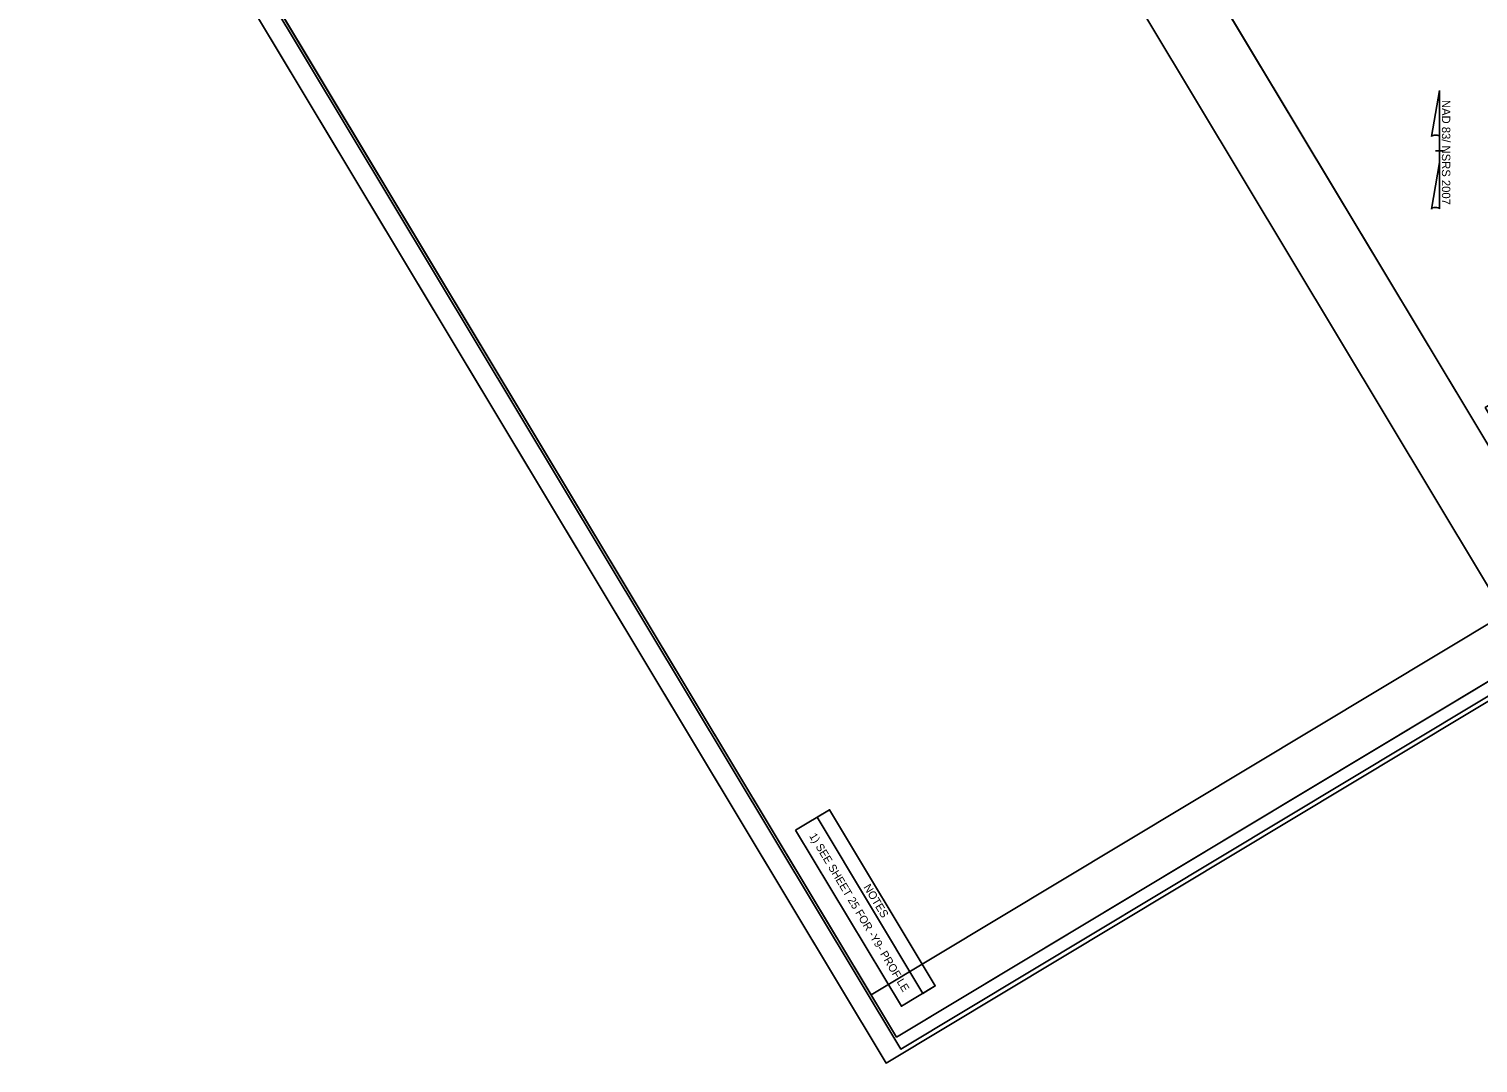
# Model space of a CAD drawing. Extents: x 1778994 to 1781413, y 814194 to 816432.
# Drawn here: x 1778994 to 1780460, y 814194 to 815240 of the extents above; entities that cross this region are included whole.
import ezdxf

# ---------------------------------------------------------------- set-up
doc = ezdxf.new("R2010")
doc.units = 0
for name, color, linetype in [('Matchline', 7, 'Continuous'), ('Prop DSN Text', 7, 'Continuous'), ('Prop Grid Mask', 7, 'Continuous'), ('Prop North Arrow NAD83 for Plan Sheets CELL', 7, 'Continuous'), ('Sheet Clip Boundary CELL', 7, 'Continuous'), ('Sheet Cutting Line CELL', 7, 'Continuous'), ('Sheet Layout Plan Border', 7, 'Continuous'), ('Sheet Plan CELL', 7, 'Continuous'), ('Sheet Plan Layout CELL', 7, 'Continuous'), ('Sheet Plot Border Inside CELL', 7, 'Continuous'), ('Sheet Plot Border Outside CELL', 7, 'Continuous')]:
    doc.layers.add(name, color=color, linetype=linetype)

msp = doc.modelspace()

# ---------------------------------------------------------------- linework, layer by layer
at = {"layer": 'Matchline'}
msp.add_line((1779828.9, 815886.5), (1780452.5, 814848.7), dxfattribs=at)
at = {"layer": 'Prop Grid Mask'}
for points in [[(1779769.3, 814429.8), (1779876.4, 814251.7), (1779910.7, 814272.3), (1779803.7, 814450.5)], [(1779791.2, 814443), (1779898.2, 814264.8), (1779910.7, 814272.3), (1779803.7, 814450.5)]]:
    msp.add_lwpolyline(points, close=True, dxfattribs=at)
at = {"layer": 'Prop North Arrow NAD83 for Plan Sheets CELL'}
for p, q in [((1780412.6, 815131.6), (1780420.8, 815178)), ((1780420.9, 815178), (1780420.8, 815178)), ((1780420.9, 815178), (1780420.8, 815178)), ((1780420.9, 815178), (1780420.9, 815130.2)), ((1780420.9, 815105.4), (1780420.9, 815131.6)), ((1780420.9, 815130.2), (1780420.9, 815131.5)), ((1780416.9, 815117), (1780416.8, 815117)), ((1780416.9, 815117), (1780424.9, 815117)), ((1780420.4, 815117), (1780416.9, 815117)), ((1780420.9, 815105.4), (1780412.5, 815058.1)), ((1780420.9, 815058.3), (1780420.9, 815105.4))]:
    msp.add_line(p, q, dxfattribs=at)
for centre, start_param, end_param in [((1780416.8, 815131.1), 0.216388, 2.908219), ((1780416.8, 815057.9), 0.201328, 3.141593)]:
    msp.add_ellipse(centre, major_axis=(4.23, -0.03), ratio=0.461098, start_param=start_param, end_param=end_param, dxfattribs=at)
at = {"layer": 'Sheet Clip Boundary CELL'}
msp.add_lwpolyline([(1779124.7, 815463.4), (1779845.7, 814263.4), (1780549.9, 814686.5), (1780452.5, 814848.7), (1780452.5, 814848.7), (1779828.9, 815886.5)], close=True, dxfattribs=at)
at = {"layer": 'Sheet Cutting Line CELL'}
msp.add_line((1778993.9, 815637.4), (1779860.9, 814194.3), dxfattribs=at)
at = {"layer": 'Sheet Layout Plan Border'}
msp.add_lwpolyline([(1779124.7, 815463.4), (1779845.7, 814263.4), (1780549.9, 814686.5), (1780452.5, 814848.7), (1779828.9, 815886.5)], close=True, dxfattribs=at)
at = {"layer": 'Sheet Plan CELL'}
for p, q in [((1779871.5, 814220.5), (1779098.9, 815506.3)), ((1780642.9, 814684), (1779871.5, 814220.5))]:
    msp.add_line(p, q, dxfattribs=at)
msp.add_lwpolyline([(1780771.5, 814761.3), (1779998.9, 816047), (1779098.9, 815506.3), (1779871.5, 814220.5)], close=True, dxfattribs=at)
at = {"layer": 'Sheet Plan Layout CELL'}
for points in [[(1780639.9, 816432.2), (1779739.9, 815891.4), (1780512.5, 814605.7), (1781231.2, 815037.5), (1781108, 815242.6), (1781289.3, 815351.5)], [(1779998.9, 816047.1), (1779098.9, 815506.3), (1779871.5, 814220.5), (1780590.2, 814652.4), (1780467, 814857.4), (1780648.3, 814966.4)]]:
    msp.add_lwpolyline(points, close=True, dxfattribs=at)
at = {"layer": 'Sheet Plot Border Inside CELL'}
msp.add_lwpolyline([(1779017.7, 815636.5), (1779875.8, 814208.5), (1780780.1, 814751.9), (1779922, 816179.9)], close=True, dxfattribs=at)
at = {"layer": 'Sheet Plot Border Outside CELL'}
msp.add_lwpolyline([(1778993.9, 815637.4), (1779860.9, 814194.3), (1780799.5, 814758.3), (1779932.5, 816201.3)], close=True, dxfattribs=at)

# ---------------------------------------------------------------- texts
at = {"layer": 'Prop DSN Text'}
for s, height, p in [('1) SEE SHEET 25 FOR -Y9- PROFILE', 8, (1779782.9, 814424)), ('NOTES', 8.1, (1779837.8, 814372.3))]:
    msp.add_text(s, height=height, rotation=301, dxfattribs=at).set_placement(p)
at = {"layer": 'Prop North Arrow NAD83 for Plan Sheets CELL'}
msp.add_text('NAD 83/ NSRS 2007', height=8.5, rotation=270, dxfattribs=at).set_placement((1780423.2, 815168.5))

doc.saveas('drawing.dxf')
